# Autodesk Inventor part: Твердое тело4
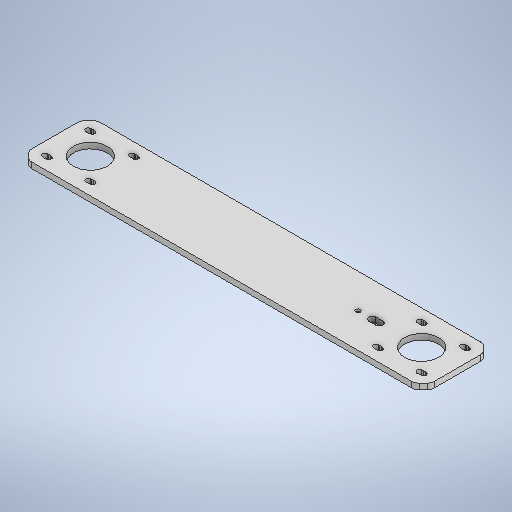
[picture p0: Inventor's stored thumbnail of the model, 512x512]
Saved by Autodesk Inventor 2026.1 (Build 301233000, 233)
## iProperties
Created: 2026-01
Part Number: Твердое тело4
Material: Типовые
Document SubType Name: Modeling
Designer: Yury Melnikov
Density: 1 g/cm^3
Appearance: По умолчанию
Author: Yury Melnikov
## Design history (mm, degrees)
derived "Nema17H44.ipt"
sketch "Эскиз1"
  geometry: L1 (222.172, -24)-(212.172, -24); L2 (219.672, -26.5)-(214.672, -26.5); L3 (214.672, -21.5)-(219.672, -21.5); L4 (-7.828, -40.172)-(-7.828, -7.828) reference; C1 r 12 at (249.172, -24) reference; C2 r 1.65 at (204.672, -24); A1 r 2.5 centre (219.672, -24) between (219.672, -26.5) and (219.672, -21.5); A2 r 2.5 centre (214.672, -24) between (214.672, -21.5) and (214.672, -26.5); 4 further points
  constraints: 8 end point, 7 point on circle, 4 tangent, 3 centre point, 2 horizontal alignment, 2 midpoint, 2 point on line, 1 horizontal, 1 parallel
  dimensions: "d1" = 10 distance of L1.start L1.end; "d2" = 2.5 radius of A2; "d3" = 27 distance of C1.centre point (222.172, -24); "d6" = 3.3 diameter of C2; "d7" = 10 distance of C2.centre A2.centre
extrude "Выдавливание1" cut sketch "Эскиз1" distance "d4" = 10; taper "d5" = 0 deg
chamfer "Фаска1" distance "d8" = 2.4; stored, may be unused: second distance "d9" = 2, angle "d10" = 45 deg
feature "Твердое тело4::Nema17H44.ipt" dims "d0" = 10
tag "Элемент создания тегов1"
node "Твердое тело4"
